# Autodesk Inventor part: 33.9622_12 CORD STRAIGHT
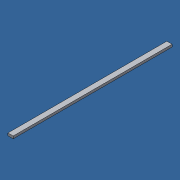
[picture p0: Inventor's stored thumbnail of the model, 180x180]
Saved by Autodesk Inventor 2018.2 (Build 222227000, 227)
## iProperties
Created: 2018-05
Part Number: 33.9622_12 CORD STRAIGHT
Material: Generic
Document SubType Name: Modeling
Designer: amoles
Density: 1 g/cm^3
Appearance: White
Author: amoles
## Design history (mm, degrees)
sketch "Sketch1"
  geometry: L1 (-3.5, 1.65)-(3.5, 1.65); L2 (3.5, 1.65)-(3.5, -1.65); L3 (3.5, -1.65)-(-3.5, -1.65); L4 (-3.5, -1.65)-(-3.5, 1.65); 3 further points
  constraints: 8 end point, 2 midpoint, 2 parallel, 1 horizontal, 1 horizontal alignment, 1 perpendicular, 1 vertical alignment
  dimensions: "d0" = 7 distance of L1.start L1.end; "d1" = 3.3 distance of L1.end L2.end
extrude "Extrusion1" new body sketch "Sketch1" distance "d2" = 212.725; taper "d3" = 0 deg
body "Solid1"
